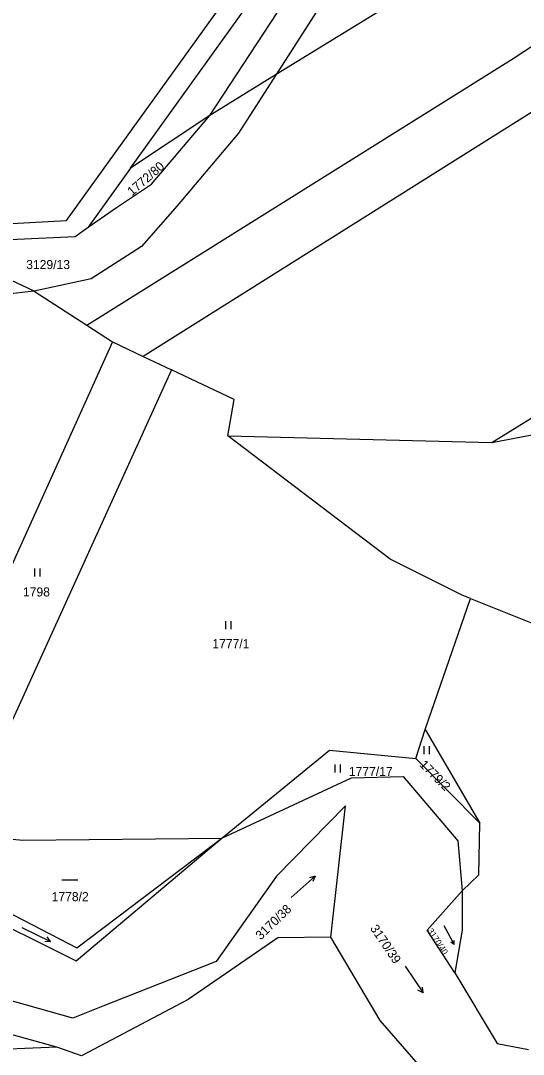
# Model space of a CAD drawing. Extents: x -755528 to -748832, y -1118122 to -1111095.
# Drawn here: x -752280.8 to -752186.6, y -1117673.1 to -1117479.4 of the extents above; entities that cross this region are included whole.
import ezdxf

# ---------------------------------------------------------------- set-up
doc = ezdxf.new("R2010")
doc.units = 0
for name, color, linetype in [('DZ_DO_PUPFL', 7, 'Continuous'), ('DZ_NAD_ZPF', 7, 'Continuous'), ('TZ_UMVŽST', 7, 'Continuous')]:
    doc.layers.add(name, color=color, linetype=linetype)

msp = doc.modelspace()

# ---------------------------------------------------------------- linework, layer by layer
at = {"layer": 'DZ_NAD_ZPF'}
for p, q in [((-752260.21, -1117507), (-752176.49, -1117390.58)), ((-752192.46, -1117558.43), (-752066.92, -1117480.91)), ((-752232.94, -1117489.5), (-752245.38, -1117497.13)), ((-752245.38, -1117497.13), (-752260.21, -1117507)), ((-752260.21, -1117507), (-752268.21, -1117518.12)), ((-752278.32, -1117530.07), (-752282.66, -1117528.04)), ((-752278.32, -1117530.07), (-752283.9, -1117530.72)), ((-752278.32, -1117530.07), (-752268.42, -1117536.48)), ((-752268.42, -1117536.48), (-752263.61, -1117539.6)), ((-752263.61, -1117539.6), (-752301.61, -1117623.67)), ((-752263.61, -1117539.6), (-752257.88, -1117542.3)), ((-752257.88, -1117542.3), (-752252.54, -1117544.82)), ((-752252.54, -1117544.82), (-752292.17, -1117631.87)), ((-752242, -1117557.23), (-752192.46, -1117558.43)), ((-752204.99, -1117612.25), (-752196.45, -1117587.67)), ((-752206.73, -1117617.71), (-752204.99, -1117612.25)), ((-752204.99, -1117612.25), (-752194.73, -1117629.8)), ((-752194.73, -1117629.8), (-752206.73, -1117617.71))]:
    msp.add_line(p, q, dxfattribs=at)
for points in [[(-752245.38, -1117497.13), (-752225.12, -1117466.23), (-752202.52, -1117436.44), (-752164.44, -1117398.12), (-752146.18, -1117379.45), (-752138.35, -1117366.46)], [(-752126.38, -1117386.7), (-752138.03, -1117389.76), (-752159.09, -1117402.3), (-752196.61, -1117439.82), (-752219.94, -1117469.17), (-752232.94, -1117489.5)], [(-752313.16, -1117515.54), (-752298.6, -1117518.26), (-752272.26, -1117516.81), (-752210.97, -1117431.77), (-752187.52, -1117397.56)], [(-752111.12, -1117413.38), (-752157.34, -1117441.59), (-752191.1, -1117463.81), (-752232.94, -1117489.5)], [(-752268.42, -1117536.48), (-752188.49, -1117486.48), (-752136.27, -1117452.16), (-752101.06, -1117430.97)], [(-752095.65, -1117440.44), (-752152.6, -1117475.4), (-752161.07, -1117481.52), (-752257.88, -1117542.3)], [(-752232.94, -1117489.5), (-752239.97, -1117500.48), (-752251.47, -1117514.08), (-752258.19, -1117521.74), (-752267.63, -1117527.75), (-752278.32, -1117530.07)], [(-752268.21, -1117518.12), (-752262.87, -1117514.38), (-752256.29, -1117510.06), (-752245.38, -1117497.13)], [(-752282.87, -1117520.4), (-752270.63, -1117519.82), (-752268.21, -1117518.12)], [(-752192.46, -1117558.43), (-752145.4, -1117549.43), (-752122.6, -1117551.15), (-752065.95, -1117539.11)], [(-752242, -1117557.23), (-752240.8, -1117550.37), (-752252.54, -1117544.82)], [(-752196.45, -1117587.67), (-752198.01, -1117587.04), (-752211.55, -1117580.3), (-752242, -1117557.23)], [(-752196.45, -1117587.67), (-752168.97, -1117598.69), (-752149.39, -1117606.23)], [(-752243.1, -1117632.59), (-752222.95, -1117616.09), (-752206.73, -1117617.71)], [(-752243.1, -1117632.59), (-752218.8, -1117621.3), (-752209.1, -1117621.05), (-752198.82, -1117633.12), (-752198.06, -1117642.5)], [(-752222.65, -1117651.17), (-752219.94, -1117626.58), (-752232.85, -1117639.74), (-752244.18, -1117655.74), (-752265.43, -1117664.08), (-752271.05, -1117666.32), (-752286.43, -1117662.06), (-752290.45, -1117657.27), (-752300.04, -1117651.67)], [(-752198.06, -1117642.5), (-752194.92, -1117639.47), (-752194.73, -1117629.8)], [(-752292.17, -1117631.87), (-752280.46, -1117632.97), (-752243.1, -1117632.59)], [(-752293.44, -1117634.65), (-752290.8, -1117645.49), (-752270.4, -1117655.61), (-752243.1, -1117632.59)], [(-752293.44, -1117634.65), (-752290.49, -1117642.72), (-752270.3, -1117653.16), (-752243.1, -1117632.59)], [(-752199.43, -1117657.88), (-752204.59, -1117649.88), (-752198.06, -1117642.5)], [(-752198.06, -1117642.5), (-752198.05, -1117649.86), (-752199.43, -1117657.88)], [(-752222.65, -1117651.17), (-752232.63, -1117651.32), (-752249.45, -1117662.87), (-752269.46, -1117673.43), (-752274.04, -1117671.81)], [(-752198.09, -1117683.1), (-752199.95, -1117682.2), (-752213.4, -1117666.76), (-752222.65, -1117651.17)], [(-752274.04, -1117671.81), (-752289.09, -1117672.42), (-752303.34, -1117658.29), (-752300.04, -1117651.67)], [(-752274.04, -1117671.81), (-752288.13, -1117667.89), (-752300.04, -1117651.67)], [(-752199.43, -1117657.88), (-752191.49, -1117671.11), (-752185.61, -1117672.25)]]:
    msp.add_lwpolyline(points, dxfattribs=at)
at = {"layer": 'TZ_UMVŽST'}
for p, q in [((-752278.161, -1117583.54), (-752278.161, -1117582.04)), ((-752277.16, -1117583.54), (-752277.16, -1117582.04)), ((-752242.381, -1117593.45), (-752242.381, -1117591.95)), ((-752241.38, -1117593.45), (-752241.38, -1117591.95)), ((-752205.191, -1117616.86), (-752205.191, -1117615.36)), ((-752204.19, -1117616.86), (-752204.19, -1117615.36)), ((-752221.831, -1117620.28), (-752221.831, -1117618.78)), ((-752220.83, -1117620.28), (-752220.83, -1117618.78)), ((-752230.091, -1117643.752), (-752225.632, -1117639.738)), ((-752225.632, -1117639.738), (-752226.694, -1117640.019)), ((-752225.632, -1117639.738), (-752226.023, -1117640.764)), ((-752273.128, -1117640.43), (-752270.128, -1117640.43)), ((-752280.625, -1117649.37), (-752275.232, -1117652)), ((-752201.474, -1117649.005), (-752199.525, -1117652.521)), ((-752275.232, -1117652), (-752275.89, -1117651.121)), ((-752275.232, -1117652), (-752276.33, -1117652.023)), ((-752199.525, -1117652.521), (-752200.136, -1117652.111)), ((-752199.525, -1117652.521), (-752199.549, -1117651.785)), ((-752208.725, -1117656.632), (-752205.37, -1117661.606)), ((-752205.37, -1117661.606), (-752206.332, -1117661.076)), ((-752205.37, -1117661.606), (-752205.501, -1117660.516))]:
    msp.add_line(p, q, dxfattribs=at)

# ---------------------------------------------------------------- texts
at = {"layer": 'DZ_DO_PUPFL'}
for s, height, rotation, p in [('1772/80', 1.7, 41, (-752259.932, -1117512.321)), ('1779/2', 1.7, 315, (-752206.161, -1117618.991)), ('3170/38', 1.7, 43.999997, (-752235.819, -1117651.791)), ('3170/39', 1.7, 304, (-752215.384, -1117649.515)), ('3170/40', 1.14, 303, (-752204.576, -1117649.965))]:
    msp.add_text(s, height=height, rotation=rotation, dxfattribs=at).set_placement(p)
for s, p in [('3129/13', (-752279.8, -1117525.94)), ('1798', (-752280.41, -1117587.31)), ('1777/1', (-752244.89, -1117597)), ('1777/17', (-752219.29, -1117620.96)), ('1778/2', (-752275.03, -1117644.42))]:
    msp.add_text(s, height=1.7, dxfattribs=at).set_placement(p)

doc.saveas('drawing.dxf')
